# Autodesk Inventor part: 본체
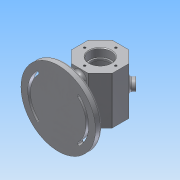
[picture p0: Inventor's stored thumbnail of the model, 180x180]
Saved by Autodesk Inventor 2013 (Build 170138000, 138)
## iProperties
Created: 2017-06
Part Number: 본체
Material: 알루미늄 6061
Document SubType Name: Modeling
Designer: Administrator
Density: 2.71 g/cm^3
Mass: 562.243 g
Surface Area: 566.157 cm^2
Volume: 207.47 cm^3
Author: Administrator
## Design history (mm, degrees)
sketch "스케치1"
  geometry: L1 (12.426, 30)-(30, 12.426); L2 (30, 12.426)-(30, -12.426); L3 (30, -12.426)-(12.426, -30); L4 (12.426, -30)-(-12.426, -30); L5 (-12.426, -30)-(-30, -12.426); L6 (-30, -12.426)-(-30, 12.426); L7 (-30, 12.426)-(-12.426, 30); L8 (-12.426, 30)-(12.426, 30); 2 further points
  constraints: 16 end point, 1 coincident, 1 horizontal, 17 other
  dimensions: "d0" = 60 distance between parallel lines of L3 L7
extrude "돌출1" new body sketch "스케치1" stored distance "d1" = 70; taper "d2" = 0 deg
sketch "스케치2"
  geometry: C1 r 25 at (0, 0); 1 further point
  constraints: 1 centre point, 1 coincident
  dimensions: "d3" = 50 diameter of C1
extrude "돌출2" cut sketch "스케치2" stored distance "d4" = 40; taper "d5" = 0 deg
sketch "스케치3"
  geometry: 2 further points
  constraints: 1 coincident
hole "구멍1" sketch "스케치3" at (0, 0) diameter "d6" = 28; stored, may be unused: countersink angle "d10" = 90 deg, drill point angle "d12" = 0 deg; dims "d7" = 6, "d8" = 32, "d9" = 12, "d11" = 15
node "작업 평면1"
sketch "스케치4"
  geometry: C1 r 8 at (-12.426, 35); 1 further point
  constraints: 1 centre point, 1 coincident
  dimensions: "d14" = 16 diameter of C1
extrude "돌출3" join sketch "스케치4" stored distance "d16" = 40; taper "d17" = 0 deg
node "작업 평면2"
sketch "스케치5"
  geometry: C1 r 55 at (0, 0); 1 further point
  constraints: 1 centre point, 1 coincident
  dimensions: "d19" = 110 diameter of C1
extrude "돌출4" join sketch "스케치5" distance "d20" = 10; taper "d21" = 0 deg
fillet "모깎기1" dims "d22" = 3
sketch "스케치6"
  geometry: C1 r 52 at (0, 0) reference; A1 r 48 centre (0, 0) between (-33.941, 33.941) and (-33.941, -33.941); A2 r 38 centre (0, 0) between (-26.87, 26.87) and (-26.87, -26.87); A3 r 5 centre (-30.406, 30.406) between (-26.87, 26.87) and (-33.941, 33.941); A4 r 5 centre (-30.406, -30.406) between (-33.941, -33.941) and (-26.87, -26.87); A5 r 2 centre (-30.406, -30.406) between (-31.82, -31.82) and (-28.991, -28.991); A6 r 2 centre (-30.406, 30.406) between (-28.991, 28.991) and (-31.82, 31.82); A7 r 41 centre (0, 0) between (-28.991, 28.991) and (-28.991, -28.991); A8 r 45 centre (0, 0) between (-31.82, 31.82) and (-31.82, -31.82)
  constraints: 16 point on circle, 8 centre point, 6 coincident, 6 tangent, 1 vertical alignment
  dimensions: "d23" = 96 diameter of A1; "d24" = 76 diameter of A2; "d25" = 90 deg dimension on C1.centre A4.centre A3.centre; "d26" = 2 radius of A5; "d27" = 2 radius of A6
extrude "돌출5" cut sketch "스케치6" distance "d28" = 3; taper "d29" = 0 deg
extrude "돌출6" cut sketch "스케치6" stored distance "d30" = 3; taper "d31" = 0 deg
sketch "스케치7"
  geometry: L1 (-5, -24)-(5, -24); L2 (5, -24)-(5, 24); L3 (5, 24)-(-5, 24); L4 (-5, 24)-(-5, -24); L5 (-5, -24)-(5, 24); L6 (5, -24)-(-5, 24); C1 r 52 at (0, 0) reference; 2 further points
  constraints: 12 end point, 4 midpoint, 2 horizontal alignment, 2 parallel, 1 horizontal, 1 perpendicular, 4 other
  dimensions: "d32" = 10 distance of L3.end L2.end; "d33" = 48 distance of L2.end L1.end
extrude "돌출7" join sketch "스케치7" stored distance "d34" = 3; taper "d35" = 0 deg
fillet "모깎기2" dims "d36" = 5
sketch "스케치8"
  geometry: C1 r 8 at (0, 0) reference; C2 r 4 at (0, 0)
  constraints: 1 centre point, 1 coincident
  dimensions: "d37" = 8 diameter of C2
extrude "돌출8" cut sketch "스케치8" stored distance "d38" = 3; taper "d39" = 0 deg
chamfer "모따기1" distance "d40" = 1; stored, may be unused: second distance "d41" = 2, angle "d42" = 45 deg
fillet "모깎기3" dims "d43" = 0.3
fillet "모깎기4" dims "d44" = 3
fillet "모깎기5" dims "d45" = 1
sketch "스케치9"
  geometry: 2 further points
  constraints: 1 coincident, 1 other
feature "엠보싱1" sketch "스케치9" dims "d0" = 60, "d46" = 0.5, "d47" = 0
sketch "스케치10"
  geometry: C1 r 17 at (0, 0) reference; 1 further point
  constraints: 1 vertical alignment
  dimensions: "d48" = 23 distance of C1.centre point (0, 23)
hole "구멍2" sketch "스케치10" at (0, 23) diameter "d49" = 3.242; stored, may be unused: countersink angle "d53" = 90 deg, drill point angle "d55" = 118 deg; dims "d50" = 8, "d51" = 32, "d52" = 12, "d54" = 10
fillet "모깎기6" dims "d59" = 3
node "솔리드1"
mirror "대칭1"
mirror "대칭2"
pattern_circular "원형 패턴1" dims angle "d57" = 360 deg
mirror "대칭3"
other parameters: "d13" = 7, "d18" = -62
